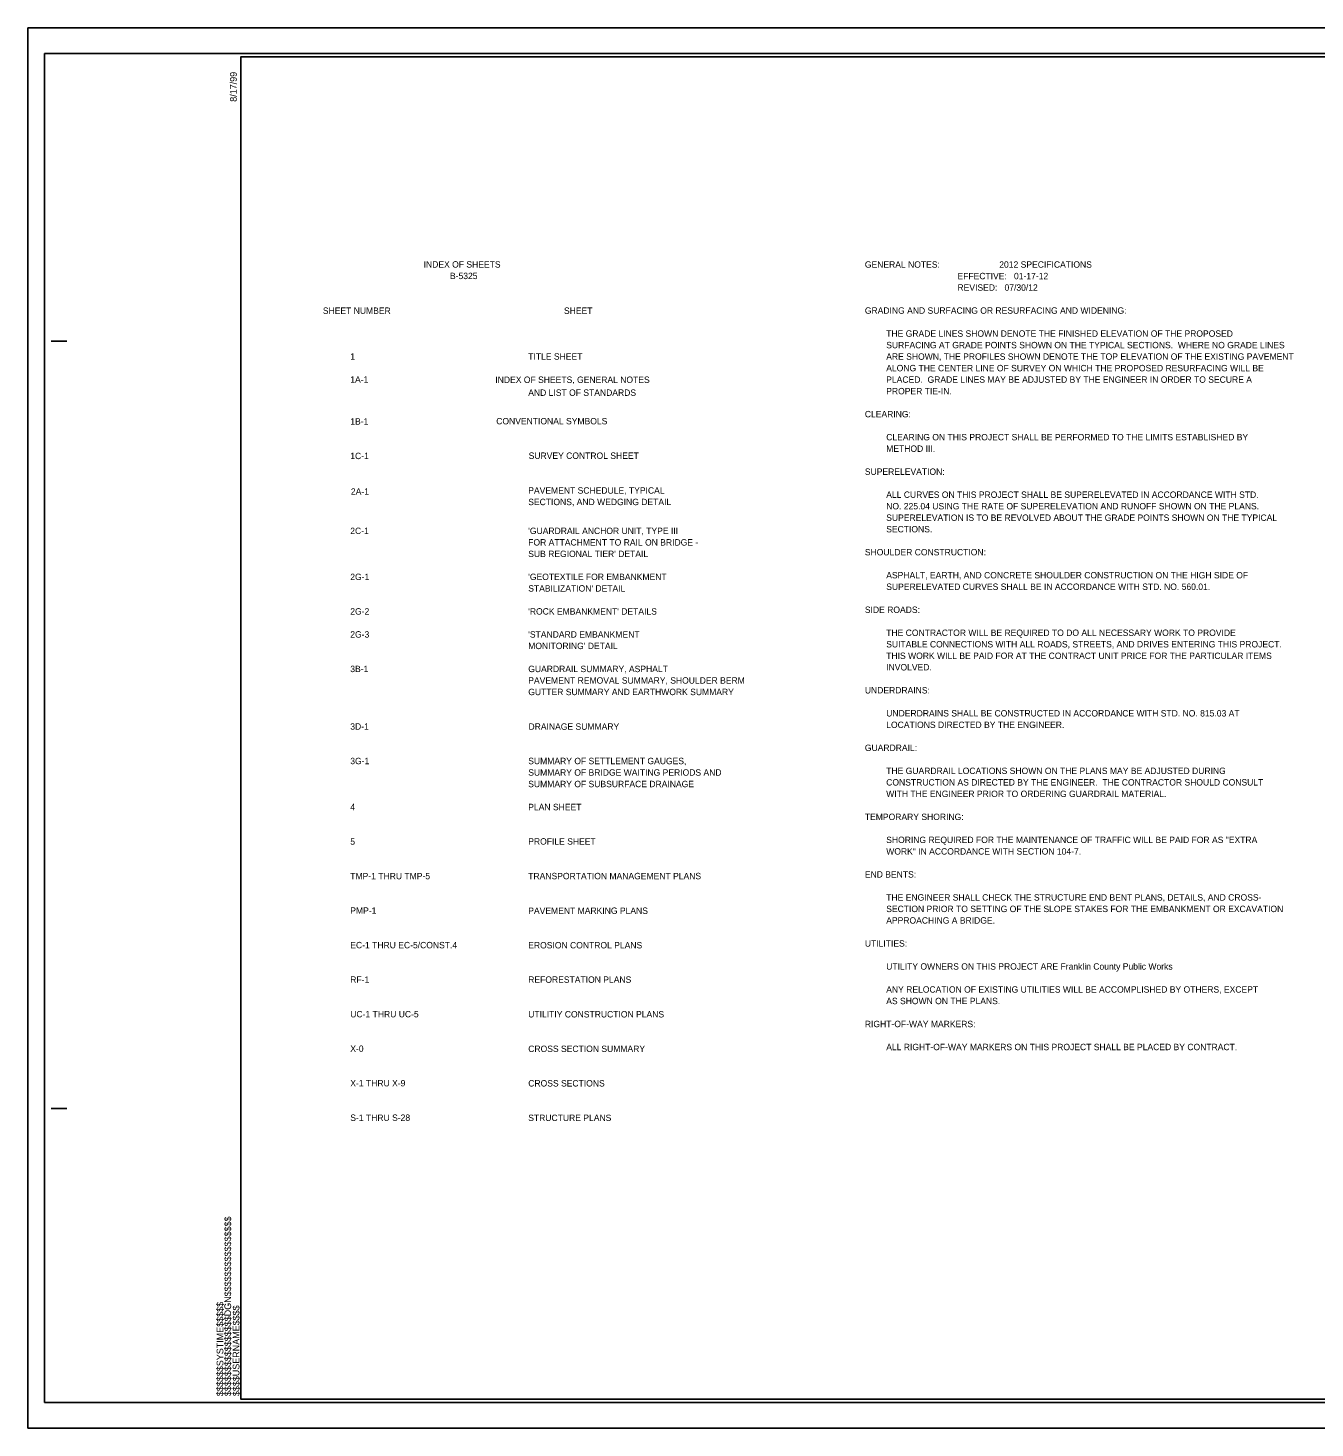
# Model space of a CAD drawing. Extents: x 9834 to 11517, y 9978 to 11072.
# Drawn here: x 9834 to 10840, y 9978 to 11072 of the extents above; entities that cross this region are included whole.
import ezdxf

# ---------------------------------------------------------------- set-up
doc = ezdxf.new("R2010")
doc.units = 0
for name, color, linetype in [('Default', 7, 'Continuous'), ('Sheet Cutting Line CELL', 7, 'Continuous'), ('Sheet Plan CELL', 7, 'Continuous'), ('Sheet Plot Border Inside CELL', 7, 'Continuous'), ('Sheet Plot Border Outside CELL', 7, 'Continuous')]:
    doc.layers.add(name, color=color, linetype=linetype)

msp = doc.modelspace()

# ---------------------------------------------------------------- linework, layer by layer
at = {"layer": 'Sheet Cutting Line CELL'}
for p, q in [((11517, 11072.5), (9833.5, 11072.5)), ((9833.5, 11072.5), (9833.5, 9977.5)), ((9833.5, 9977.5), (11517, 9977.5))]:
    msp.add_line(p, q, dxfattribs=at)
at = {"layer": 'Sheet Plan CELL'}
for p, q in [((10000, 11050), (10000, 11050)), ((9851.5, 10827.5), (9864, 10827.5)), ((9851.5, 10227.5), (9864, 10227.5)), ((10000, 10000), (10000, 10000))]:
    msp.add_line(p, q, dxfattribs=at)
msp.add_lwpolyline([(11500, 11050), (10000, 11050), (10000, 10000), (11500, 10000)], close=True, dxfattribs=at)
at = {"layer": 'Sheet Plot Border Inside CELL'}
msp.add_lwpolyline([(9846.5, 9997.5), (11512.5, 9997.5), (11512.5, 11052.5), (9846.5, 11052.5)], close=True, dxfattribs=at)
at = {"layer": 'Sheet Plot Border Outside CELL'}
msp.add_lwpolyline([(9833.5, 9977.5), (11517, 9977.5), (11517, 11072.5), (9833.5, 11072.5)], close=True, dxfattribs=at)

# ---------------------------------------------------------------- texts
at = {"layer": 'Default'}
for s, p in [('          INDEX OF SHEETS', (10124.4, 10885.1)), ('GENERAL NOTES:                         2012 SPECIFICATIONS', (10488.1, 10885)), ('          B-5325', (10145, 10876.1)), ('                                       EFFECTIVE:   01-17-12', (10488.1, 10876)), ('                                       REVISED:   07/30/12', (10488.1, 10867)), ('      SHEET NUMBER', (10053, 10848.9)), ('      SHEET', (10241.6, 10848.9)), ('GRADING AND SURFACING OR RESURFACING AND WIDENING:  ', (10488.1, 10849)), ('         THE GRADE LINES SHOWN DENOTE THE FINISHED ELEVATION OF THE PROPOSED ', (10488.1, 10831)), ('         SURFACING AT GRADE POINTS SHOWN ON THE TYPICAL SECTIONS.  WHERE NO GRADE LINES ', (10488.1, 10822)), ('1', (10085.6, 10813.1)), ('TITLE SHEET', (10224.8, 10813.1)), ('         ARE SHOWN, THE PROFILES SHOWN DENOTE THE TOP ELEVATION OF THE EXISTING PAVEMENT ', (10488.1, 10813)), ('         ALONG THE CENTER LINE OF SURVEY ON WHICH THE PROPOSED RESURFACING WILL BE ', (10488.1, 10804)), ('1A-1', (10085.6, 10795.1)), ('        INDEX OF SHEETS, GENERAL NOTES ', (10184.2, 10794.9)), ('         PLACED.  GRADE LINES MAY BE ADJUSTED BY THE ENGINEER IN ORDER TO SECURE A ', (10488.1, 10795)), ('AND LIST OF STANDARDS', (10224.8, 10784.8)), ('         PROPER TIE-IN.  ', (10488.1, 10786)), ('1B-1', (10085.6, 10762.3)), ('        CONVENTIONAL SYMBOLS', (10184.9, 10762.5)), ('CLEARING:  ', (10488.1, 10768)), ('         CLEARING ON THIS PROJECT SHALL BE PERFORMED TO THE LIMITS ESTABLISHED BY ', (10488.1, 10750)), ('         METHOD III.', (10488.1, 10741)), ('1C-1                             ', (10085.6, 10735.3)), ('SURVEY CONTROL SHEET', (10225.1, 10735.5)), ('SUPERELEVATION:  ', (10488.1, 10723)), ('2A-1    ', (10086.1, 10707.5)), ('PAVEMENT SCHEDULE, TYPICAL ', (10224.8, 10708.3)), ('         ALL CURVES ON THIS PROJECT SHALL BE SUPERELEVATED IN ACCORDANCE WITH STD. ', (10488.1, 10705)), ('SECTIONS, AND WEDGING DETAIL', (10224.8, 10699.3)), ('         NO. 225.04 USING THE RATE OF SUPERELEVATION AND RUNOFF SHOWN ON THE PLANS.', (10488.1, 10696)), ('         SUPERELEVATION IS TO BE REVOLVED ABOUT THE GRADE POINTS SHOWN ON THE TYPICAL ', (10488.1, 10687)), ('2C-1 ', (10085.6, 10676.7)), ("'GUARDRAIL ANCHOR UNIT, TYPE III", (10224.8, 10676.7)), ('         SECTIONS.  ', (10488.1, 10678)), ('FOR ATTACHMENT TO RAIL ON BRIDGE -', (10224.8, 10667.7)), ("SUB REGIONAL TIER' DETAIL", (10224.8, 10658.7)), ('SHOULDER CONSTRUCTION:  ', (10488.1, 10660)), ('2G-1', (10085.6, 10640.7)), ("'GEOTEXTILE FOR EMBANKMENT ", (10224.8, 10640.7)), ('         ASPHALT, EARTH, AND CONCRETE SHOULDER CONSTRUCTION ON THE HIGH SIDE OF', (10488.1, 10642)), ("STABILIZATION' DETAIL", (10224.8, 10631.7)), ('         SUPERELEVATED CURVES SHALL BE IN ACCORDANCE WITH STD. NO. 560.01.', (10488.1, 10633)), ('2G-2', (10085.6, 10613.7)), ("'ROCK EMBANKMENT' DETAILS", (10224.8, 10613.7)), ('SIDE ROADS:  ', (10488.1, 10615)), ('2G-3', (10085.6, 10595.7)), ("'STANDARD EMBANKMENT ", (10224.8, 10595.7)), ('         THE CONTRACTOR WILL BE REQUIRED TO DO ALL NECESSARY WORK TO PROVIDE ', (10488.1, 10597)), ("MONITORING' DETAIL", (10224.8, 10586.7)), ('         SUITABLE CONNECTIONS WITH ALL ROADS, STREETS, AND DRIVES ENTERING THIS PROJECT.  ', (10488.1, 10588)), ('         THIS WORK WILL BE PAID FOR AT THE CONTRACT UNIT PRICE FOR THE PARTICULAR ITEMS ', (10488.1, 10579)), ('3B-1', (10085.6, 10568.7)), ('GUARDRAIL SUMMARY, ASPHALT ', (10224.8, 10568.7)), ('         INVOLVED.  ', (10488.1, 10570)), ('PAVEMENT REMOVAL SUMMARY, SHOULDER BERM ', (10224.8, 10559.7)), ('UNDERDRAINS:  ', (10488.1, 10552)), ('GUTTER SUMMARY AND EARTHWORK SUMMARY ', (10224.8, 10550.7)), ('         UNDERDRAINS SHALL BE CONSTRUCTED IN ACCORDANCE WITH STD. NO. 815.03 AT ', (10488.1, 10534)), ('3D-1                            ', (10085.6, 10523.7)), ('DRAINAGE SUMMARY', (10225, 10523.6)), ('         LOCATIONS DIRECTED BY THE ENGINEER.  ', (10488.1, 10525)), ('GUARDRAIL:  ', (10488.1, 10507)), ('3G-1 ', (10085.6, 10496.7)), ('SUMMARY OF SETTLEMENT GAUGES, ', (10224.8, 10496.7)), ('SUMMARY OF BRIDGE WAITING PERIODS AND ', (10224.8, 10487.7)), ('         THE GUARDRAIL LOCATIONS SHOWN ON THE PLANS MAY BE ADJUSTED DURING ', (10488.1, 10489)), ('SUMMARY OF SUBSURFACE DRAINAGE', (10224.8, 10478.7)), ('         CONSTRUCTION AS DIRECTED BY THE ENGINEER.  THE CONTRACTOR SHOULD CONSULT', (10488.1, 10480)), ('         WITH THE ENGINEER PRIOR TO ORDERING GUARDRAIL MATERIAL.', (10488.1, 10471)), ('4', (10085.6, 10460.7)), ('PLAN SHEET', (10224.8, 10460.7)), ('TEMPORARY SHORING:  ', (10488.1, 10453)), ('5                                ', (10085.6, 10433.7)), ('PROFILE SHEET', (10224.8, 10433.8)), ('         SHORING REQUIRED FOR THE MAINTENANCE OF TRAFFIC WILL BE PAID FOR AS "EXTRA ', (10488.1, 10435)), ('         WORK" IN ACCORDANCE WITH SECTION 104-7.  ', (10488.1, 10426)), ('TMP-1 THRU TMP-5                ', (10085.6, 10406.7)), ('TRANSPORTATION MANAGEMENT PLANS', (10224.8, 10406.7)), ('END BENTS:  ', (10488.1, 10408)), ('         THE ENGINEER SHALL CHECK THE STRUCTURE END BENT PLANS, DETAILS, AND CROSS-', (10488.1, 10390)), ('PMP-1                           ', (10085.6, 10379.7)), ('PAVEMENT MARKING PLANS', (10224.8, 10379.6)), ('         SECTION PRIOR TO SETTING OF THE SLOPE STAKES FOR THE EMBANKMENT OR EXCAVATION ', (10488.1, 10381)), ('         APPROACHING A BRIDGE.  ', (10488.1, 10372)), ('UTILITIES:  ', (10488.1, 10354)), ('EC-1 THRU EC-5/CONST.4', (10085.6, 10352.7)), ('EROSION CONTROL PLANS', (10224.8, 10352.6)), ('         UTILITY OWNERS ON THIS PROJECT ARE Franklin County Public Works', (10488.1, 10336)), ('RF-1                             ', (10085.6, 10325.7)), ('REFORESTATION PLANS', (10224.8, 10325.7)), ('         ANY RELOCATION OF EXISTING UTILITIES WILL BE ACCOMPLISHED BY OTHERS, EXCEPT ', (10488.1, 10318)), ('         AS SHOWN ON THE PLANS.  ', (10488.1, 10309)), ('UC-1 THRU UC-5           ', (10085.6, 10298.7)), ('UTILITIY CONSTRUCTION PLANS', (10224.8, 10298.6)), ('RIGHT-OF-WAY MARKERS:  ', (10488.1, 10291)), ('X-0                              ', (10085.6, 10271.7)), ('CROSS SECTION SUMMARY', (10224.8, 10271.6)), ('         ALL RIGHT-OF-WAY MARKERS ON THIS PROJECT SHALL BE PLACED BY CONTRACT.  ', (10488.1, 10273)), ('X-1 THRU X-9                     ', (10085.6, 10244.7)), ('CROSS SECTIONS', (10224.8, 10244.6)), ('S-1 THRU S-28                    ', (10085.6, 10217.7)), ('STRUCTURE PLANS', (10224.8, 10217.6))]:
    msp.add_text(s, height=5, dxfattribs=at).set_placement(p)
at = {"layer": 'Sheet Plan CELL'}
for s, p in [('8/17/99', (9996.8, 11014.8)), ('$$$$$$$$$$$$$$$$DGN$$$$$$$$$$$$$$$$', (9992.4, 10002.4)), ('$$$$$$SYSTIME$$$$$', (9986.3, 10002.4)), ('$$$$USERNAME$$$$', (9998.9, 10002.4))]:
    msp.add_text(s, height=5.25, rotation=90, dxfattribs=at).set_placement(p)

doc.saveas('drawing.dxf')
